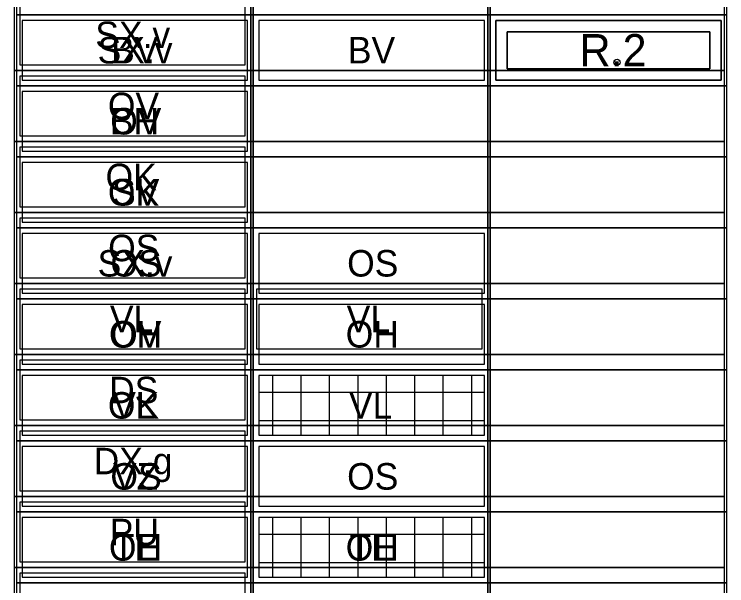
# Model space of a CAD drawing. Extents: x -557692 to -550384, y -1187532 to -1181973.
# Drawn here: x -552820.9 to -552444.7, y -1183366.2 to -1183064.5 of the extents above; entities that cross this region are included whole.
import ezdxf

# ---------------------------------------------------------------- set-up
doc = ezdxf.new("R2010")
doc.units = 0
for name, color, linetype in [('LEG_2a', 7, 'Continuous'), ('LEG_2b', 7, 'Continuous'), ('LEG_4_KOO', 7, 'Continuous')]:
    doc.layers.add(name, color=color, linetype=linetype)

msp = doc.modelspace()

# ---------------------------------------------------------------- linework, layer by layer
at = {"layer": 'LEG_2a'}
for points in [[(-552820.95, -1183094.08), (-552695.95, -1183094.08), (-552695.95, -1183056.58), (-552820.95, -1183056.58)], [(-552695.95, -1183094.08), (-552570.95, -1183094.08), (-552570.95, -1183056.58), (-552695.95, -1183056.58)], [(-552570.95, -1183094.08), (-552445.95, -1183094.08), (-552445.95, -1183056.58), (-552570.95, -1183056.58)], [(-552817.95, -1183091.08), (-552698.95, -1183091.08), (-552698.95, -1183059.58), (-552817.95, -1183059.58)], [(-552817.95, -1183091.08), (-552698.95, -1183091.08), (-552698.95, -1183059.58), (-552817.95, -1183059.58)], [(-552820.95, -1183131.58), (-552695.95, -1183131.58), (-552695.95, -1183094.08), (-552820.95, -1183094.08)], [(-552695.95, -1183131.58), (-552570.95, -1183131.58), (-552570.95, -1183094.08), (-552695.95, -1183094.08)], [(-552570.95, -1183131.58), (-552445.95, -1183131.58), (-552445.95, -1183094.08), (-552570.95, -1183094.08)], [(-552817.95, -1183128.58), (-552698.95, -1183128.58), (-552698.95, -1183097.08), (-552817.95, -1183097.08)], [(-552817.95, -1183128.58), (-552698.95, -1183128.58), (-552698.95, -1183097.08), (-552817.95, -1183097.08)], [(-552820.95, -1183169.08), (-552695.95, -1183169.08), (-552695.95, -1183131.58), (-552820.95, -1183131.58)], [(-552695.95, -1183169.08), (-552570.95, -1183169.08), (-552570.95, -1183131.58), (-552695.95, -1183131.58)], [(-552570.95, -1183169.08), (-552445.95, -1183169.08), (-552445.95, -1183131.58), (-552570.95, -1183131.58)], [(-552817.95, -1183166.08), (-552698.95, -1183166.08), (-552698.95, -1183134.58), (-552817.95, -1183134.58)], [(-552817.95, -1183166.08), (-552698.95, -1183166.08), (-552698.95, -1183134.58), (-552817.95, -1183134.58)], [(-552820.95, -1183206.58), (-552695.95, -1183206.58), (-552695.95, -1183169.08), (-552820.95, -1183169.08)], [(-552695.95, -1183206.58), (-552570.95, -1183206.58), (-552570.95, -1183169.08), (-552695.95, -1183169.08)], [(-552570.95, -1183206.58), (-552445.95, -1183206.58), (-552445.95, -1183169.08), (-552570.95, -1183169.08)], [(-552817.95, -1183203.58), (-552698.95, -1183203.58), (-552698.95, -1183172.08), (-552817.95, -1183172.08)], [(-552817.95, -1183203.58), (-552698.95, -1183203.58), (-552698.95, -1183172.08), (-552817.95, -1183172.08)], [(-552820.95, -1183244.08), (-552695.95, -1183244.08), (-552695.95, -1183206.58), (-552820.95, -1183206.58)], [(-552695.95, -1183244.08), (-552570.95, -1183244.08), (-552570.95, -1183206.58), (-552695.95, -1183206.58)], [(-552570.95, -1183244.08), (-552445.95, -1183244.08), (-552445.95, -1183206.58), (-552570.95, -1183206.58)], [(-552817.95, -1183241.08), (-552698.95, -1183241.08), (-552698.95, -1183209.58), (-552817.95, -1183209.58)], [(-552817.95, -1183241.08), (-552698.95, -1183241.08), (-552698.95, -1183209.58), (-552817.95, -1183209.58)], [(-552692.95, -1183241.08), (-552573.95, -1183241.08), (-552573.95, -1183209.58), (-552692.95, -1183209.58)], [(-552692.95, -1183241.08), (-552657.3, -1183241.08), (-552573.95, -1183241.08), (-552573.95, -1183209.58), (-552692.95, -1183209.58)], [(-552820.95, -1183281.58), (-552695.95, -1183281.58), (-552695.95, -1183244.08), (-552820.95, -1183244.08)], [(-552695.95, -1183281.58), (-552570.95, -1183281.58), (-552570.95, -1183244.08), (-552695.95, -1183244.08)], [(-552570.95, -1183281.58), (-552445.95, -1183281.58), (-552445.95, -1183244.08), (-552570.95, -1183244.08)], [(-552817.95, -1183278.58), (-552698.95, -1183278.58), (-552698.95, -1183247.08), (-552817.95, -1183247.08)], [(-552817.95, -1183278.58), (-552698.95, -1183278.58), (-552698.95, -1183247.08), (-552817.95, -1183247.08)], [(-552820.95, -1183319.08), (-552695.95, -1183319.08), (-552695.95, -1183281.58), (-552820.95, -1183281.58)], [(-552695.95, -1183319.08), (-552570.95, -1183319.08), (-552570.95, -1183281.58), (-552695.95, -1183281.58)], [(-552570.95, -1183319.08), (-552445.95, -1183319.08), (-552445.95, -1183281.58), (-552570.95, -1183281.58)], [(-552817.95, -1183316.08), (-552698.95, -1183316.08), (-552698.95, -1183284.58), (-552817.95, -1183284.58)], [(-552817.95, -1183316.08), (-552698.95, -1183316.08), (-552698.95, -1183284.58), (-552817.95, -1183284.58)], [(-552820.95, -1183356.58), (-552695.95, -1183356.58), (-552695.95, -1183319.08), (-552820.95, -1183319.08)], [(-552695.95, -1183356.58), (-552570.95, -1183356.58), (-552570.95, -1183319.08), (-552695.95, -1183319.08)], [(-552570.95, -1183356.58), (-552445.95, -1183356.58), (-552445.95, -1183319.08), (-552570.95, -1183319.08)], [(-552817.95, -1183353.58), (-552698.95, -1183353.58), (-552698.95, -1183322.08), (-552817.95, -1183322.08)], [(-552817.95, -1183353.58), (-552698.95, -1183353.58), (-552698.95, -1183322.08), (-552817.95, -1183322.08)], [(-552820.95, -1183394.08), (-552695.95, -1183394.08), (-552695.95, -1183356.58), (-552820.95, -1183356.58)], [(-552695.95, -1183394.08), (-552570.95, -1183394.08), (-552570.95, -1183356.58), (-552695.95, -1183356.58)], [(-552570.95, -1183394.08), (-552445.95, -1183394.08), (-552445.95, -1183356.58), (-552570.95, -1183356.58)], [(-552817.95, -1183391.08), (-552698.95, -1183391.08), (-552698.95, -1183359.58), (-552817.95, -1183359.58)], [(-552817.95, -1183391.08), (-552698.95, -1183391.08), (-552698.95, -1183359.58), (-552817.95, -1183359.58)]]:
    msp.add_lwpolyline(points, close=True, dxfattribs=at)
at = {"layer": 'LEG_2b'}
for p, q in [((-552684.4, -1183286.68), (-552684.4, -1183255.18)), ((-552669.4, -1183286.68), (-552669.4, -1183255.18)), ((-552654.4, -1183286.68), (-552654.4, -1183255.18)), ((-552639.4, -1183286.68), (-552639.4, -1183255.18)), ((-552624.4, -1183286.68), (-552624.4, -1183255.18)), ((-552609.4, -1183286.68), (-552609.4, -1183255.18)), ((-552594.4, -1183286.68), (-552594.4, -1183255.18)), ((-552579.4, -1183286.68), (-552579.4, -1183255.18)), ((-552691.73, -1183263.92), (-552572.73, -1183263.92)), ((-552691.73, -1183278.92), (-552572.73, -1183278.92)), ((-552684.4, -1183361.68), (-552684.4, -1183330.18)), ((-552669.4, -1183361.68), (-552669.4, -1183330.18)), ((-552654.4, -1183361.68), (-552654.4, -1183330.18)), ((-552639.4, -1183361.68), (-552639.4, -1183330.18)), ((-552624.4, -1183361.68), (-552624.4, -1183330.18)), ((-552609.4, -1183361.68), (-552609.4, -1183330.18)), ((-552594.4, -1183361.68), (-552594.4, -1183330.18)), ((-552579.4, -1183361.68), (-552579.4, -1183330.18)), ((-552691.73, -1183338.92), (-552572.73, -1183338.92)), ((-552691.73, -1183353.92), (-552572.73, -1183353.92))]:
    msp.add_line(p, q, dxfattribs=at)
for points in [[(-552819.73, -1183064.68), (-552694.73, -1183064.68), (-552694.73, -1183027.18), (-552819.73, -1183027.18)], [(-552694.73, -1183064.68), (-552569.73, -1183064.68), (-552569.73, -1183027.18), (-552694.73, -1183027.18)], [(-552569.73, -1183064.68), (-552444.73, -1183064.68), (-552444.73, -1183027.18), (-552569.73, -1183027.18)], [(-552819.73, -1183102.18), (-552694.73, -1183102.18), (-552694.73, -1183064.68), (-552819.73, -1183064.68)], [(-552694.73, -1183102.18), (-552569.73, -1183102.18), (-552569.73, -1183064.68), (-552694.73, -1183064.68)], [(-552569.73, -1183102.18), (-552444.73, -1183102.18), (-552444.73, -1183064.68), (-552569.73, -1183064.68)], [(-552816.73, -1183099.18), (-552697.73, -1183099.18), (-552697.73, -1183067.68), (-552816.73, -1183067.68)], [(-552816.73, -1183099.18), (-552697.73, -1183099.18), (-552697.73, -1183067.68), (-552816.73, -1183067.68)], [(-552819.73, -1183139.68), (-552694.73, -1183139.68), (-552694.73, -1183102.18), (-552819.73, -1183102.18)], [(-552694.73, -1183139.68), (-552569.73, -1183139.68), (-552569.73, -1183102.18), (-552694.73, -1183102.18)], [(-552569.73, -1183139.68), (-552444.73, -1183139.68), (-552444.73, -1183102.18), (-552569.73, -1183102.18)], [(-552816.73, -1183136.68), (-552697.73, -1183136.68), (-552697.73, -1183105.18), (-552816.73, -1183105.18)], [(-552816.73, -1183136.68), (-552697.73, -1183136.68), (-552697.73, -1183105.18), (-552816.73, -1183105.18)], [(-552819.73, -1183177.18), (-552694.73, -1183177.18), (-552694.73, -1183139.68), (-552819.73, -1183139.68)], [(-552694.73, -1183177.18), (-552569.73, -1183177.18), (-552569.73, -1183139.68), (-552694.73, -1183139.68)], [(-552569.73, -1183177.18), (-552444.73, -1183177.18), (-552444.73, -1183139.68), (-552569.73, -1183139.68)], [(-552816.73, -1183174.18), (-552697.73, -1183174.18), (-552697.73, -1183142.68), (-552816.73, -1183142.68)], [(-552816.73, -1183174.18), (-552697.73, -1183174.18), (-552697.73, -1183142.68), (-552816.73, -1183142.68)], [(-552819.73, -1183214.68), (-552694.73, -1183214.68), (-552694.73, -1183177.18), (-552819.73, -1183177.18)], [(-552694.73, -1183214.68), (-552569.73, -1183214.68), (-552569.73, -1183177.18), (-552694.73, -1183177.18)], [(-552569.73, -1183214.68), (-552444.73, -1183214.68), (-552444.73, -1183177.18), (-552569.73, -1183177.18)], [(-552816.73, -1183211.68), (-552697.73, -1183211.68), (-552697.73, -1183180.18), (-552816.73, -1183180.18)], [(-552816.73, -1183211.68), (-552697.73, -1183211.68), (-552697.73, -1183180.18), (-552816.73, -1183180.18)], [(-552691.73, -1183211.68), (-552572.73, -1183211.68), (-552572.73, -1183180.18), (-552691.73, -1183180.18)], [(-552691.73, -1183211.68), (-552572.73, -1183211.68), (-552572.73, -1183180.18), (-552601.11, -1183180.18), (-552691.73, -1183180.18)], [(-552819.73, -1183252.18), (-552694.73, -1183252.18), (-552694.73, -1183214.68), (-552819.73, -1183214.68)], [(-552694.73, -1183252.18), (-552569.73, -1183252.18), (-552569.73, -1183214.68), (-552694.73, -1183214.68)], [(-552569.73, -1183252.18), (-552444.73, -1183252.18), (-552444.73, -1183214.68), (-552569.73, -1183214.68)], [(-552816.73, -1183249.18), (-552697.73, -1183249.18), (-552697.73, -1183217.68), (-552816.73, -1183217.68)], [(-552816.73, -1183249.18), (-552697.73, -1183249.18), (-552697.73, -1183217.68), (-552816.73, -1183217.68)], [(-552691.73, -1183249.18), (-552572.73, -1183249.18), (-552572.73, -1183217.68), (-552691.73, -1183217.68)], [(-552691.73, -1183249.18), (-552572.73, -1183249.18), (-552572.73, -1183217.68), (-552601.11, -1183217.68), (-552691.73, -1183217.68)], [(-552819.73, -1183289.68), (-552694.73, -1183289.68), (-552694.73, -1183252.18), (-552819.73, -1183252.18)], [(-552694.73, -1183289.68), (-552569.73, -1183289.68), (-552569.73, -1183252.18), (-552694.73, -1183252.18)], [(-552569.73, -1183289.68), (-552444.73, -1183289.68), (-552444.73, -1183252.18), (-552569.73, -1183252.18)], [(-552816.73, -1183286.68), (-552697.73, -1183286.68), (-552697.73, -1183255.18), (-552816.73, -1183255.18)], [(-552816.73, -1183286.68), (-552697.73, -1183286.68), (-552697.73, -1183255.18), (-552816.73, -1183255.18)], [(-552691.73, -1183286.68), (-552572.73, -1183286.68), (-552572.73, -1183255.18), (-552691.73, -1183255.18)], [(-552691.73, -1183286.68), (-552572.73, -1183286.68), (-552572.73, -1183255.18), (-552691.73, -1183255.18)], [(-552819.73, -1183327.18), (-552694.73, -1183327.18), (-552694.73, -1183289.68), (-552819.73, -1183289.68)], [(-552694.73, -1183327.18), (-552569.73, -1183327.18), (-552569.73, -1183289.68), (-552694.73, -1183289.68)], [(-552569.73, -1183327.18), (-552444.73, -1183327.18), (-552444.73, -1183289.68), (-552569.73, -1183289.68)], [(-552816.73, -1183324.18), (-552697.73, -1183324.18), (-552697.73, -1183292.68), (-552816.73, -1183292.68)], [(-552816.73, -1183324.18), (-552697.73, -1183324.18), (-552697.73, -1183292.68), (-552816.73, -1183292.68)], [(-552819.73, -1183364.68), (-552694.73, -1183364.68), (-552694.73, -1183327.18), (-552819.73, -1183327.18)], [(-552694.73, -1183364.68), (-552569.73, -1183364.68), (-552569.73, -1183327.18), (-552694.73, -1183327.18)], [(-552569.73, -1183364.68), (-552444.73, -1183364.68), (-552444.73, -1183327.18), (-552569.73, -1183327.18)], [(-552816.73, -1183361.68), (-552697.73, -1183361.68), (-552697.73, -1183330.18), (-552816.73, -1183330.18)], [(-552816.73, -1183361.68), (-552697.73, -1183361.68), (-552697.73, -1183330.18), (-552816.73, -1183330.18)], [(-552691.73, -1183361.68), (-552572.73, -1183361.68), (-552572.73, -1183330.18), (-552691.73, -1183330.18)], [(-552691.73, -1183361.68), (-552572.73, -1183361.68), (-552572.73, -1183330.18), (-552691.73, -1183330.18)], [(-552819.73, -1183402.18), (-552694.73, -1183402.18), (-552694.73, -1183364.68), (-552819.73, -1183364.68)], [(-552694.73, -1183402.18), (-552569.73, -1183402.18), (-552569.73, -1183364.68), (-552694.73, -1183364.68)], [(-552569.73, -1183402.18), (-552444.73, -1183402.18), (-552444.73, -1183364.68), (-552569.73, -1183364.68)]]:
    msp.add_lwpolyline(points, close=True, dxfattribs=at)
at = {"layer": 'LEG_4_KOO'}
for p, q in [((-552566.73, -1183099.18), (-552566.73, -1183067.68)), ((-552566.73, -1183067.68), (-552447.73, -1183067.68)), ((-552447.73, -1183067.68), (-552447.73, -1183099.18)), ((-552447.73, -1183099.18), (-552566.73, -1183099.18))]:
    msp.add_line(p, q, dxfattribs=at)
for points in [[(-552819.73, -1183102.18), (-552694.73, -1183102.18), (-552694.73, -1183064.68), (-552819.73, -1183064.68)], [(-552694.73, -1183102.18), (-552569.73, -1183102.18), (-552569.73, -1183064.68), (-552694.73, -1183064.68)], [(-552569.73, -1183102.18), (-552444.73, -1183102.18), (-552444.73, -1183064.68), (-552569.73, -1183064.68)], [(-552816.73, -1183099.18), (-552697.73, -1183099.18), (-552697.73, -1183067.68), (-552816.73, -1183067.68)], [(-552816.73, -1183099.18), (-552697.73, -1183099.18), (-552697.73, -1183067.68), (-552816.73, -1183067.68)], [(-552691.73, -1183099.18), (-552572.73, -1183099.18), (-552572.73, -1183067.68), (-552691.73, -1183067.68)], [(-552691.73, -1183099.18), (-552572.73, -1183099.18), (-552572.73, -1183067.68), (-552601.11, -1183067.68), (-552691.73, -1183067.68)], [(-552566.73, -1183099.18), (-552447.73, -1183099.18), (-552447.73, -1183067.68), (-552476.11, -1183067.68), (-552566.73, -1183067.68)], [(-552560.73, -1183073.68), (-552560.73, -1183093.18), (-552453.73, -1183093.18), (-552453.73, -1183073.68)], [(-552819.73, -1183139.68), (-552694.73, -1183139.68), (-552694.73, -1183102.18), (-552819.73, -1183102.18)], [(-552694.73, -1183139.68), (-552569.73, -1183139.68), (-552569.73, -1183102.18), (-552694.73, -1183102.18)], [(-552569.73, -1183139.68), (-552444.73, -1183139.68), (-552444.73, -1183102.18), (-552569.73, -1183102.18)], [(-552816.73, -1183136.68), (-552697.73, -1183136.68), (-552697.73, -1183105.18), (-552816.73, -1183105.18)], [(-552816.73, -1183136.68), (-552697.73, -1183136.68), (-552697.73, -1183105.18), (-552816.73, -1183105.18)], [(-552819.73, -1183177.18), (-552694.73, -1183177.18), (-552694.73, -1183139.68), (-552819.73, -1183139.68)], [(-552694.73, -1183177.18), (-552569.73, -1183177.18), (-552569.73, -1183139.68), (-552694.73, -1183139.68)], [(-552569.73, -1183177.18), (-552444.73, -1183177.18), (-552444.73, -1183139.68), (-552569.73, -1183139.68)], [(-552816.73, -1183174.18), (-552697.73, -1183174.18), (-552697.73, -1183142.68), (-552816.73, -1183142.68)], [(-552816.73, -1183174.18), (-552697.73, -1183174.18), (-552697.73, -1183142.68), (-552816.73, -1183142.68)], [(-552819.73, -1183214.68), (-552694.73, -1183214.68), (-552694.73, -1183177.18), (-552819.73, -1183177.18)], [(-552694.73, -1183214.68), (-552569.73, -1183214.68), (-552569.73, -1183177.18), (-552694.73, -1183177.18)], [(-552569.73, -1183214.68), (-552444.73, -1183214.68), (-552444.73, -1183177.18), (-552569.73, -1183177.18)], [(-552816.73, -1183211.68), (-552697.73, -1183211.68), (-552697.73, -1183180.18), (-552816.73, -1183180.18)], [(-552816.73, -1183211.68), (-552697.73, -1183211.68), (-552697.73, -1183180.18), (-552816.73, -1183180.18)], [(-552819.73, -1183252.18), (-552694.73, -1183252.18), (-552694.73, -1183214.68), (-552819.73, -1183214.68)], [(-552694.73, -1183252.18), (-552569.73, -1183252.18), (-552569.73, -1183214.68), (-552694.73, -1183214.68)], [(-552569.73, -1183252.18), (-552444.73, -1183252.18), (-552444.73, -1183214.68), (-552569.73, -1183214.68)], [(-552816.73, -1183249.18), (-552697.73, -1183249.18), (-552697.73, -1183217.68), (-552816.73, -1183217.68)], [(-552816.73, -1183249.18), (-552697.73, -1183249.18), (-552697.73, -1183217.68), (-552816.73, -1183217.68)], [(-552819.73, -1183289.68), (-552694.73, -1183289.68), (-552694.73, -1183252.18), (-552819.73, -1183252.18)], [(-552694.73, -1183289.68), (-552569.73, -1183289.68), (-552569.73, -1183252.18), (-552694.73, -1183252.18)], [(-552569.73, -1183289.68), (-552444.73, -1183289.68), (-552444.73, -1183252.18), (-552569.73, -1183252.18)], [(-552816.73, -1183286.68), (-552697.73, -1183286.68), (-552697.73, -1183255.18), (-552816.73, -1183255.18)], [(-552816.73, -1183286.68), (-552697.73, -1183286.68), (-552697.73, -1183255.18), (-552816.73, -1183255.18)], [(-552819.73, -1183327.18), (-552694.73, -1183327.18), (-552694.73, -1183289.68), (-552819.73, -1183289.68)], [(-552694.73, -1183327.18), (-552569.73, -1183327.18), (-552569.73, -1183289.68), (-552694.73, -1183289.68)], [(-552569.73, -1183327.18), (-552444.73, -1183327.18), (-552444.73, -1183289.68), (-552569.73, -1183289.68)], [(-552816.73, -1183324.18), (-552697.73, -1183324.18), (-552697.73, -1183292.68), (-552816.73, -1183292.68)], [(-552816.73, -1183324.18), (-552697.73, -1183324.18), (-552697.73, -1183292.68), (-552816.73, -1183292.68)], [(-552691.73, -1183324.18), (-552572.73, -1183324.18), (-552572.73, -1183292.68), (-552691.73, -1183292.68)], [(-552691.73, -1183324.18), (-552572.73, -1183324.18), (-552572.73, -1183292.68), (-552601.11, -1183292.68), (-552691.73, -1183292.68)], [(-552819.73, -1183364.68), (-552694.73, -1183364.68), (-552694.73, -1183327.18), (-552819.73, -1183327.18)], [(-552694.73, -1183364.68), (-552569.73, -1183364.68), (-552569.73, -1183327.18), (-552694.73, -1183327.18)], [(-552569.73, -1183364.68), (-552444.73, -1183364.68), (-552444.73, -1183327.18), (-552569.73, -1183327.18)], [(-552816.73, -1183361.68), (-552697.73, -1183361.68), (-552697.73, -1183330.18), (-552816.73, -1183330.18)], [(-552816.73, -1183361.68), (-552697.73, -1183361.68), (-552697.73, -1183330.18), (-552816.73, -1183330.18)], [(-552691.73, -1183361.68), (-552572.73, -1183361.68), (-552572.73, -1183330.18), (-552691.73, -1183330.18)], [(-552691.73, -1183361.68), (-552572.73, -1183361.68), (-552572.73, -1183330.18), (-552601.11, -1183330.18), (-552691.73, -1183330.18)], [(-552819.73, -1183402.18), (-552694.73, -1183402.18), (-552694.73, -1183364.68), (-552819.73, -1183364.68)], [(-552694.73, -1183402.18), (-552569.73, -1183402.18), (-552569.73, -1183364.68), (-552694.73, -1183364.68)], [(-552569.73, -1183402.18), (-552444.73, -1183402.18), (-552444.73, -1183364.68), (-552569.73, -1183364.68)]]:
    msp.add_lwpolyline(points, close=True, dxfattribs=at)
for points in [[(-552566.73, -1183099.18), (-552447.73, -1183099.18), (-552447.73, -1183067.68), (-552476.11, -1183067.68), (-552566.73, -1183067.68), (-552566.73, -1183099.18)], [(-552453.73, -1183073.68), (-552453.73, -1183093.18), (-552560.73, -1183093.18), (-552560.73, -1183073.68), (-552453.73, -1183073.68)]]:
    msp.add_lwpolyline(points, dxfattribs=at)
msp.add_circle((-552502.64, -1183089.83), 1.64, dxfattribs=at)

# ---------------------------------------------------------------- texts
at = {"layer": 'LEG_2a'}
for s, p in [('SX.v', (-552778.14, -1183082.33)), ('OV', (-552771.52, -1183119.83)), ('OK', (-552772.73, -1183157.33)), ('OS', (-552771.39, -1183194.83)), ('VL', (-552770.43, -1183232.33)), ('VL', (-552645.43, -1183232.33)), ('DS', (-552770.88, -1183269.83)), ('DX.g', (-552779.03, -1183307.33)), ('PU', (-552770.54, -1183344.83))]:
    msp.add_text(s, height=14, dxfattribs=at).set_placement(p)
at = {"layer": 'LEG_2b'}
for s, p in [('SX.v', (-552776.93, -1183090.43)), ('OV', (-552770.3, -1183127.93)), ('OK', (-552771.51, -1183165.43)), ('OS', (-552770.18, -1183202.93)), ('OS', (-552645.18, -1183202.93)), ('OH', (-552770.94, -1183240.43)), ('OH', (-552645.94, -1183240.43)), ('VL', (-552769.21, -1183277.93)), ('VL', (-552644.21, -1183277.93)), ('VZ', (-552768.83, -1183315.43)), ('TE', (-552768.96, -1183352.93)), ('TE', (-552643.96, -1183352.93))]:
    msp.add_text(s, height=14, dxfattribs=at).set_placement(p)
at = {"layer": 'LEG_4_KOO'}
for s, height, p in [('BV', 14, (-552769.79, -1183090.43)), ('BV', 14, (-552644.79, -1183090.43)), ('R.2', 17, (-552522.44, -1183091.91)), ('BH', 14, (-552770.43, -1183127.93)), ('SV', 14, (-552769.29, -1183165.43)), ('SX.v', 14, (-552776.93, -1183202.93)), ('OV', 14, (-552770.3, -1183240.43)), ('OK', 14, (-552771.51, -1183277.93)), ('OS', 14, (-552770.18, -1183315.43)), ('OS', 14, (-552645.18, -1183315.43)), ('OH', 14, (-552770.94, -1183352.93)), ('OH', 14, (-552645.94, -1183352.93))]:
    msp.add_text(s, height=height, dxfattribs=at).set_placement(p)

doc.saveas('drawing.dxf')
